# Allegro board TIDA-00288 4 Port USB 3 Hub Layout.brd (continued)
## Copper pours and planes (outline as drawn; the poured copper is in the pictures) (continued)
VBUS_IN on TOP: 1.78,5.56 1.65,5.69 1.65,6.45 1.78,6.57 5.97,6.57 6.1,6.45 6.1,5.69 5.97,5.56
VBUS_IN on BOTTOM: 1.27,21.34 1.4,21.46 1.52,21.46 1.78,21.21 1.78,9.02 3.17,7.62 3.17,5.33 3.94,4.57 14.48,4.57 16.76,6.86 16.76,12.83 21.21,17.27 30.48,17.27 34.92,12.83 34.92,8.76 34.67,8.51 34.67,5.56 35.31,4.93 35.31,2.03 35.56,1.78 41.66,1.78 41.91,2.03 41.91,3.43 42.8,4.32 43.31,3.81 43.31,1.52 42.93,1.14 34.32,1.14 34.04,1.42 34.04,3.81 33.02,4.83 33.02,8.26 33.66,8.89 33.66,11.94 29.59,16 25.63,16 25.02,15.39 25.02,13.46 23.75,12.19 20.95,12.19 20.42,11.66 20.42,11.3 19.68,11.3 18.92,10.54 18.92,4.45 15.75,1.27 1.52,1.27 1.27,1.52
VBUS_OUT_PORT_3 on BOTTOM: 46.23,21.72 46.1,21.72 45.87,21.49 45.87,21.31 45.47,20.9 44.53,20.9 44.32,20.7 44.32,20.07 44.45,19.94 45.97,19.94 46.23,20.19 46.23,20.83 46.35,20.96 46.35,21.59
VBUS_OUT_PORT_4 on BOTTOM: 24,21.72 23.9,21.72 23.77,21.59 23.77,21.18 23.5,20.9 22.73,20.9 22.68,20.96 22.35,20.96 22.1,20.7 22.1,20.07 22.23,19.94 23.75,19.94 24,20.19 24,20.83 24.13,20.96 24.13,21.59
VBUS_P1_FB on BOTTOM: 52.32,16.89 50.16,16.89 50.04,16.76 50.04,16 53.85,12.19 54.61,12.19 54.86,12.45 54.86,14.22 53.59,14.22 52.7,15.11 52.7,16.51
VBUS_P2_FB on BOTTOM: 59.18,28.45 59.18,27.18 59.82,26.54 59.82,25.53 60.07,25.27 61.72,25.27 61.85,25.4 61.85,28.32 61.59,28.58 59.31,28.58
VBUS_P3_FB on BOTTOM: 36.96,28.45 36.96,27.18 37.59,26.54 37.59,25.53 37.85,25.27 39.5,25.27 39.62,25.4 39.62,28.32 39.37,28.58 37.08,28.58
VBUS_P4_FB on BOTTOM: 14.73,28.45 14.73,27.18 15.37,26.54 15.37,25.53 15.62,25.27 17.27,25.27 17.4,25.4 17.4,28.32 17.14,28.58 14.86,28.58
VBUS_PUP_FB on TOP: 6.91,5 7.04,4.87 7.04,3.65 7.22,3.48 7.62,3.48 7.62,4.87 7.93,5.18 7.93,6.4 7.83,6.5 7.06,6.5 6.91,6.35
VBUS_PUP_FB on BOTTOM: 7.04,6.22 8.18,6.22 8.18,5.13 8,4.95 7.04,4.95 6.86,5.13 6.86,6.04
BOARD_1P1V on TOP: 7.11,21.46 9.65,21.46 10.79,20.32 11.68,20.32 11.68,18.54 11.43,18.29 7.37,18.29 7.11,18.54
BOARD_1P1V on L3_PWR: 8.26,21.59 8.26,18.42 8.64,18.03 31.39,18.03 35.97,13.46 36.7,13.46 37.08,13.08 37.07,13.07 37.07,12.56 36.58,12.07 35.94,12.07 35.31,11.43 35.31,9.4 34.42,8.51 34.42,7.11 34.67,6.86 34.67,5.84 35.51,5 35.51,3.45 35.53,3.43 40.13,3.43 43.69,6.99 43.69,7.37 42.55,8.51 42.55,9.65 42.04,10.16 42.04,12.83 40.39,14.48 40.39,17.91 40.89,18.42 41.02,18.42 41.02,18.03 41.27,17.78 41.27,16.64 44.58,13.34 44.58,13.08 45.47,12.19 46.99,12.19 47.37,12.57 48.39,12.57 48.77,12.19 48.77,11.18 47.12,9.53 45.21,9.53 45.09,9.4 45.09,8.52 50.62,2.98 51.24,2.98 59.94,11.68 59.94,18.8 59.05,19.69 55.88,19.69 53.34,17.15 46.35,17.15 41.27,22.23 39.62,22.23 38.35,20.96 38.35,19.69 38.1,19.43 34.92,19.43 32.26,22.1 31.62,22.1 29.72,20.19 26.92,20.19 26.42,20.7 25.78,20.7 25.65,20.57 25.65,19.74 25.37,19.46 25.37,19.43 13.59,19.43 10.79,22.23 8.89,22.23
BOARD_3P3V on TOP: 7.37,9.27 7.37,12.32 7.49,12.45 10.79,12.45 11.05,12.19 11.05,11.68 10.41,11.05 10.41,8.13 10.29,8 8.64,8
BOARD_3P3V on BOTTOM: 35.56,2.9 35.56,2.16 35.69,2.03 41.4,2.03 41.53,2.16 41.53,3.94 40.53,4.94 39.89,4.94 37.01,7.82 36.96,7.82 36.14,7.01 36.14,6.78 38.24,4.69 38.75,4.69 39.24,4.19 39.62,4.19 39.88,3.94 39.88,3.05 39.73,2.9
BOARD_3P3V on BOTTOM: 6.35,15.11 6.35,17.27 6.6,17.53 8.64,17.53 8.76,17.4 8.76,13.72 7.75,13.72
BOARD_3P3V on L3_PWR: 6.73,16.89 6.73,14.86 8.26,13.34 8.26,8.89 8.64,8.51 10.29,8.51 10.67,8.89 10.67,10.41 15.88,15.62 29.72,15.62 34.16,11.18 34.16,8.76 33.4,8 33.4,5.72 34.54,4.57 34.54,2.03 34.67,1.91 43.05,1.91 46.35,5.21 46.35,7.24 44.58,9.02 44.58,9.53 45.09,10.03 46.86,10.03 48.26,11.43 48.26,11.68 47.88,12.07 47.57,12.07 47.19,11.68 45.47,11.68 42.04,15.11 42.04,17.53 41.66,17.91 41.15,17.91 40.89,17.65 40.89,14.61 42.55,12.95 42.55,10.67 43.05,10.16 43.05,8.76 44.2,7.62 44.2,6.73 40.39,2.92 35.56,2.92 35.18,3.3 35.18,5.21 34.37,6.02 34.37,7.7 35.08,8.41 35.08,11.86 35.79,12.57 36.58,12.57 36.78,12.78 36.78,13 36.58,13.21 35.53,13.21 31.22,17.53 7.37,17.53
BOARD_5V on TOP: 46.86,33.78 46.86,35.05 46.61,35.31 45.97,35.31 45.85,35.43 45.85,35.81 45.97,35.94 48.9,35.94 49.02,35.81 49.02,35.43 48.9,35.31 47.88,35.31 47.62,35.05 47.62,33.78
BOARD_5V on TOP: 23.77,14.2 23.77,13.44 25.13,12.08 29.1,12.08 29.21,12.19 29.21,14.22 28.32,15.11 27.71,15.11 27.71,14.35 27.58,14.22 26.54,14.22 25.78,13.46 25.27,13.46 25.15,13.59 25.15,14.1 25.27,14.22 25.27,14.4 25.2,14.48 25.02,14.48 24.89,14.35 23.93,14.35
BOARD_5V on BOTTOM: 5.84,8.26 5.84,10.8 6.1,11.05 8.64,11.05 8.76,10.92 8.76,10.54 8.38,10.16 8.38,8.76 8.76,8.38 8.76,8 8.64,7.87 8.26,7.87 7.87,7.49 7.87,7.11 7.75,6.99 6.86,6.99 6.86,7.87 6.73,8 6.1,8
BOARD_5V on BOTTOM: 46.1,35.31 48.9,35.31 49.02,35.43 49.02,36.45 45.97,36.45 45.97,35.43
BOARD_5V on L3_PWR: 1.14,1.4 1.14,37.97 1.4,38.23 65.91,38.23 66.17,37.97 66.17,1.4 65.91,1.14 32.26,1.14 32.16,1.24 32.16,11.66 31.75,12.07 20.83,12.07 20.32,11.56 20.32,1.16 15.66,1.16 15.65,1.14 1.4,1.14
JACK_INSERT on TOP: 25.53,14.86 25.53,15.24 25.78,15.49 26.92,15.49 27.18,15.24 27.18,14.61 27.05,14.48 25.91,14.48
JACK_INSERT on BOTTOM: 32.38,9.02 32.13,9.27 32.13,11.68 30.35,12.07 27.94,14.48 26.16,14.48 26.04,14.61 26.04,15.37 26.16,15.49 29.46,15.49 33.27,11.68 33.27,9.53 32.77,9.02
N15348 on TOP: 4.45,9.27 3.81,9.91 3.17,9.91 3.05,10.03 3.05,11.05 3.17,11.18 4.32,11.18 4.45,11.3 4.45,13.84 4.57,13.97 5.84,13.97 5.97,13.84 5.97,9.4 5.84,9.27
N15348 on BOTTOM: 5.33,10.03 5.33,11.05 5.21,11.18 3.17,11.18 3.05,11.05 3.05,10.03 3.17,9.91 5.21,9.91
N16337 on TOP: 6.48,16.26 6.48,18.42 6.1,18.8 6.1,21.46 4.19,21.46 3.94,21.21 3.94,17.78 3.81,17.65 3.05,17.65 2.92,17.53 2.92,16.51 3.17,16.26
N16337 on BOTTOM: 5.33,16.51 5.33,17.53 5.21,17.65 3.05,17.65 2.92,17.53 2.92,16.51 3.05,16.38 5.21,16.38

Small or netless copper shapes (teardrops, artwork), in the pictures only: 2 on TOP

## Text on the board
BOTTOM: LAYER 6 - BOTTOM SIDE | 06
Board Geometry/Soldermask Bottom: SOLDERMASK BOTTOM | 06
Ref Des/Silkscreen Bottom: SILKSCREEN BOTTOM | 08
TOP: LAYER 1 - TOP SIDE | 01
Board Geometry/Soldermask Top: SOLDERMASK TOP | 05
Ref Des/Silkscreen Top: PWR | SILKSCREEN TOP | 07
L2_GND: LAYER 2 - GND PLANE | 02
L3_PWR: LAYER 3 - PWR PLANE | 03
DIMENSION: 11
PAGE_OUTLINE: 9.  MAXIMUM ALLOWABLE LINE REDUCTION TO BE | 10.  0.0044 SIGNAL LINES ON LAYER 1 & 4 TO BE | 11.  0.0043 SIGNAL LINES ON LAYER 1 & 4 TO BE | 12.  DIELECTRIC CONSTANTS ARE         CORE : 4.1 | 13.  A CROSS SECTION MOUNT AND DIGITAL PHOTO'S OF VIA'S TO BE PROVIDED | GENERAL NOTES. UNLESS OTHERWISE SPECIFIED | 1.  ALL FABRICATION ITEMS MUST MEET OR EXCEED BEST | INDUSTRY PRACTICE : IPC-A-600C (Commercial std.) | 2.  LAMINATE MATERIAL  :  FR4 POLYCLAD 370 or EQUIVALENT | 3.  COPPER WEIGHT  : Layers 2 and 3, 2oz START INTERNAL, | 4.  COPPER WEIGHT  : Layers 1 and 4, 1/2oz, START EXTERNAL, | 5.  FINISHED BOARD THICKNESS :  .062  +/- 10% | 6.  MAXIMUM WARP AND TWIST TO BE :  .005 INCH PER INCH | 7.  MINIMUM COPPER WALL THICKNESS OF PLATED-THRU | HOLES TO BE .001 INCH. THERE MUST BE 1MIL OR GREATER PLATING ON | EACH SIDE OF THE BARREL WHEN VIEWED IN THE CROSS SECTION | 8.  MINIMUM ANNULAR RING OF PLATED-THRU HOLES | TO BE .002 INCH | 20% OR .002 WHICHEVER IS SMALLER | IMPEDANCE CONTROLLED 90 OHMS DIFFERENTIAL +/- 10% | IMPEDANCE CONTROLLED 50 OHMS +/- 10% | PREPREG : 4.1 | PROCESS NOTES | 1.  EXPOSED CIRCUITRY ON OUTER LAYERS TO BE PLATED WITH : ENIG. | 2.  SOLDERMASK BOTH SIDES PER ARTWORK  :  BLACK LPI | 3.  SILKSCREEN BOTH SIDES PER ARTWORK  :  COLOR = WHITE | 4.  ALL THE VIAS (8 MIL DRILLS) NEED TO BE TENTED.
User.5: SOLDERPASTE TOP | 09
User.6: SOLDERPASTE BOTTOM | 10
User.13: FIGURE | SIZE | 8.0 | 28.0 | 55.0 | 91.0 | 59.055x33.465 | 70.87x27.559 | 94.488x39.37 | DRILL CHART: TOP to BOTTOM | ALL UNITS ARE IN MILS | TOLERANCE | +3.0/-3.0 | +0.0/-0.0 | PLATED | QTY | 348 | 36 | 1 | 8 | 2
